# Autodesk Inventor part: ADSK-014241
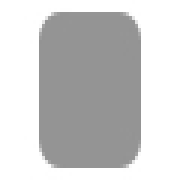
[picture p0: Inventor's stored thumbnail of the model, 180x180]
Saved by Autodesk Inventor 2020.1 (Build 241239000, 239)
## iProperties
Created: 2019-01
Part Number: ADSK-014241
Material: Stahl, weich
Document SubType Name: Modeling
Designer: lutzd
Language: de-DE
Size Designation: 5 x 39,384472 x 39,384472
Categories: <MemberInstance><Categories><Category DisplayName="Sonstige Bauteile" InternalName="5aa15e00-363f-49f2-933f-16f664388e3f" Mnemonic="OTHER"><Category DisplayName
Mass: 60.0398 g
Surface Area: 38.0412 cm^2
Volume: 7.64838 cm^3
Density: 7.85 g/cm^3
Appearance: Halbpoliert
IsCustomPart: 1
Title: end cap
Author: lutzd
Revision Number: -
DocNumber: ADSK-014241
Folder: 01 - Themengebiete\Simplification\01 - Packaging machine\ADSK-014200\Frame\
VDS_Category: 3D Komponenten
VDS_NumSchm: Autodesk
Dimensions: 39,4x39,4x5 mm
Mass: 0,06 kg
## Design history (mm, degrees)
sketch "Sketch1"
  geometry: L1 (0, 20.175)-(0, -21.446); L2 (-20.203, 0)-(20.169, 0); L3 (-19.692, 19.692)-(19.692, 19.692); L4 (19.692, 19.692)-(19.692, -19.692); L5 (19.692, -19.692)-(-19.692, -19.692); L6 (-19.692, -19.692)-(-19.692, 19.692); 1 further point
  constraints: 12 end point, 2 horizontal, 2 parallel, 2 point on line, 1 perpendicular, 1 vertical
  dimensions: "d0" = 39.38447 distance between parallel lines of L5 L3 (= height); "d1" = 19.69224 distance between parallel lines of L2 L3 (= 0.5 x height); "d2" = 39.38447 distance between parallel lines of L6 L4 (= width); "d3" = 19.69224 distance between parallel lines of L6 L1 (= 0.5 x width)
extrude "Extrusion1" new body sketch "Sketch1" distance "d4" = 5 (= thickness); taper "d5" = 0 deg
fillet "Fillet1" dims "d6" = 5 (= fillet), "d7" = 0, "fillet" = 5 [user parameter; used in 1 equation term]
chamfer "Chamfer1" distance "d8" = 0 (computed from chamfer); stored, may be unused: second distance "d9" = 2, angle "d10" = 45 deg; dims "d11" = 0, "chamfer" = 0 [user parameter; used in 1 equation term]
body "Solid1"
other parameters: "thickness" = 5 [user parameter; used in 1 equation term], "width" = 39.38447 [user parameter; used in 2 equation terms], "height" = 39.38447 [user parameter; used in 2 equation terms]
